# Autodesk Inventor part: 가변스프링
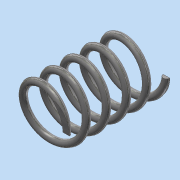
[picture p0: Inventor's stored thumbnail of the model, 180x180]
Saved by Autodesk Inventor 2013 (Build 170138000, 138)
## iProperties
Created: 2018-10
Part Number: 가변스프링
Material: 스테인리스강
Document SubType Name: Modeling
Designer: Administrator
Density: 8.08 g/cm^3
Mass: 6.30653 g
Surface Area: 15.7977 cm^2
Volume: 0.780512 cm^3
Author: Administrator
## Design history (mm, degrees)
sketch "스케치1"
  geometry: L1 (0, 0)-(0, 30.5); L2 (0, 0)-(8, 0); L3 (0, 30.5)-(8, 30.5); C1 r 1 at (8, 0)
  constraints: 6 end point, 1 centre point, 1 coincident, 1 parallel, 1 perpendicular, 1 vertical
  dimensions: "d0" = 30.5 distance of L1.start L1.end (derived); "d1" = 8 distance of L1.start L2.end; "d2" = 2 diameter of C1; "d3" = 8 distance of L1.end L3.end
feature "코일1" sketch "스케치1" pitch "d4" = 30.5 (= d0); turns "d6" = 5; dims "d5" = 30.5 (= d0), "d7" = 0, angle "d8" = 90 deg, angle "d9" = 90 deg, "d10" = 0, "d11" = 0
sketch "스케치2"
  geometry: L1 (30.5, 11)-(0, 11); L2 (0, 11)-(0, -11); L3 (0, -11)-(30.5, -11); L4 (30.5, -11)-(30.5, 11); 2 further points
  constraints: 8 end point, 2 parallel, 1 coincident, 1 horizontal, 1 midpoint, 1 perpendicular
  dimensions: "d12" = 30.5 distance of L2.end L3.end (derived); "d16" = 22 distance of L3.end L1.start
extrude "돌출1" sketch "스케치2" stored distance "d14" = 0; taper "d15" = 0 deg
node "솔리드1"
